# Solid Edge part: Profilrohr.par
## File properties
Username: ahadarics
Dokumentum tartalom típus: 0
Author: ahadarics
Last saved by: ahadarics
Revision: 85
Sűrűség: 0,000 kg/m^3
Pontosság: 0,990
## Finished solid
Body 1: solid body, 6 faces, 6 edges, 0 vertices.
  Faces by surface: cone 2, cylinder 2, plane 2
  Edges by curve: circle 6
Bounding box of the edges (mm): 26.500 x 26.500 x 353.000, from (-13.25, -13.25, -331.5) to (13.25, 13.25, 21.5).
Cylindrical faces by radius (mm): R12.5 x1, R13.25 x1
Conical faces (half-angle, radius in mm at the cone's reference point): 15 deg R12.567 x2
Planar faces by outward normal: +z 1, -z 1
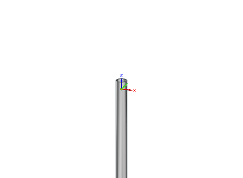
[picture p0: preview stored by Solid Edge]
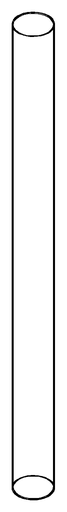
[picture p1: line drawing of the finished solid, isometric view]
